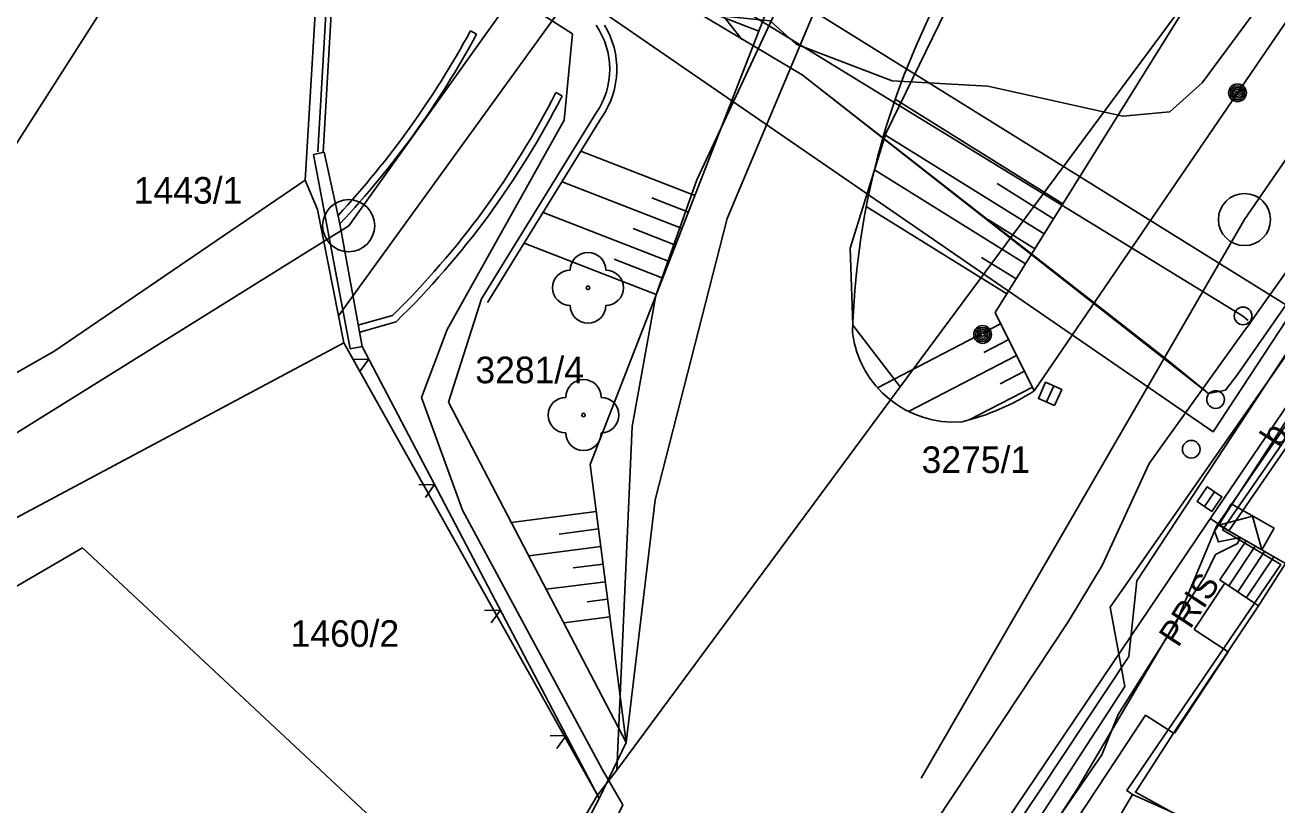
# Model space of a CAD drawing. Extents: x -601580 to 4, y -1204314 to 4.
# Drawn here: x -598974.39 to -598939.03, y -1203990.98 to -1203968.97 of the extents above; entities that cross this region are included whole.
import ezdxf

# ---------------------------------------------------------------- set-up
doc = ezdxf.new("R2010")
doc.units = 0
for name, color, linetype in [('00-EON NN', 7, 'Continuous'), ('00-INNOGY-NTL', 7, 'Continuous'), ('00-KN-HRANICE PARCEL', 7, 'Continuous'), ('00-KN-PARC. CISLA', 7, 'Continuous'), ('00-POLOHOPIS', 7, 'Continuous'), ('00-SITE KOM. KABEL', 7, 'Continuous'), ('00-VAK-KANAL-POTRUBI', 7, 'Continuous'), ('00-VAK-VODA-RAD IGIS', 7, 'Continuous'), ('11-REKONSTRUKCE  VYKOP', 7, 'Continuous'), ('11-REKONSTRUKCE VODOVOD', 7, 'Continuous'), ('11-REKONSTRUKCE VODOVOD POPIS', 7, 'Continuous'), ('Vrstva 22', 7, 'Continuous'), ('Vrstva 25', 7, 'Continuous'), ('Vrstva 27', 7, 'Continuous'), ('Vrstva 28', 7, 'Continuous'), ('Vrstva 9', 7, 'Continuous')]:
    doc.layers.add(name, color=color, linetype=linetype)

# ---------------------------------------------------------------- blocks, each defined once
blk = doc.blocks.new('6.01A_956')
at = {"layer": 'Vrstva 25'}
for radius in [0.25, 0.2, 0.15, 0.1, 0.05]:
    blk.add_circle((0, 0), radius, dxfattribs=at)
blk = doc.blocks.new('3.13_26')
at = {"layer": 'Vrstva 22'}
blk.add_circle((0, 0), 0.05, dxfattribs=at)
for centre, start, end in [((0, 0.5), 0, 180), ((-0.5, 0), 90, 270), ((0.5, 0), 270, 90), ((0, -0.5), 180, 0)]:
    blk.add_arc(centre, 0.5, start, end, dxfattribs=at)
blk = doc.blocks.new('3.13_28')
at = {"layer": 'Vrstva 22'}
blk.add_circle((0, 0), 0.05, dxfattribs=at)
for centre, start, end in [((0, 0.5), 0, 180), ((-0.5, 0), 90, 270), ((0.5, 0), 270, 90), ((0, -0.5), 180, 0)]:
    blk.add_arc(centre, 0.5, start, end, dxfattribs=at)
blk = doc.blocks.new('6.14A_100')
at = {"layer": 'Vrstva 28'}
blk.add_circle((0, 0), 0.25, dxfattribs=at)
blk = doc.blocks.new('6.14A_102')
at = {"layer": 'Vrstva 28'}
blk.add_circle((0, 0), 0.25, dxfattribs=at)
blk = doc.blocks.new('6.14A_104')
at = {"layer": 'Vrstva 28'}
blk.add_circle((0, 0), 0.25, dxfattribs=at)
blk = doc.blocks.new('6.30_46')
at = {"layer": 'Vrstva 27'}
blk.add_line((-0.25, 0), (0.25, 0), dxfattribs=at)
blk.add_lwpolyline([(-0.25, -0.25), (0.25, -0.25), (0.25, 0.25), (-0.25, 0.25)], close=True, dxfattribs=at)
blk = doc.blocks.new('6.30_48')
at = {"layer": 'Vrstva 27'}
blk.add_line((-0.25, 0.001), (0.25, -0.001), dxfattribs=at)
blk.add_lwpolyline([(-0.25, -0.25), (0.25, -0.25), (0.25, 0.25), (-0.25, 0.25)], close=True, dxfattribs=at)
blk = doc.blocks.new('6.01A_1054')
at = {"layer": 'Vrstva 25'}
for radius in [0.25, 0.2, 0.15, 0.1, 0.05]:
    blk.add_circle((0, 0), radius, dxfattribs=at)
blk = doc.blocks.new('NN630')
at = {"layer": 'Vrstva 9'}
for points in [[(-3, -700), (-703, 0)], [(-703, -700), (-703, 0), (697, 0), (697, -700)], [(-3, -700), (697, 0)], [(-703, -700), (697, -700)]]:
    blk.add_lwpolyline(points, dxfattribs=at)

msp = doc.modelspace()

# ---------------------------------------------------------------- linework, layer by layer
at = {"layer": '00-EON NN'}
for points in [[(-598970.68, -1203963.218), (-598969.283, -1203964.296), (-598968.397, -1203965.415), (-598967.498, -1203966.522), (-598965.97, -1203967.918), (-598965.479, -1203967.719), (-598961.435, -1203967.984), (-598957.276, -1203968.45), (-598953.35, -1203968.849), (-598952.613, -1203969.504), (-598949.9, -1203970.541), (-598947.199, -1203970.693), (-598943.383, -1203971.542), (-598942.059, -1203971.414), (-598941.147, -1203970.598), (-598936.353, -1203964.12), (-598934.62, -1203962.058), (-598933.364, -1203961.664), (-598929.2, -1203961.329), (-598925.224, -1203960.211), (-598924.191, -1203959.49), (-598923.41, -1203958.618), (-598917.275, -1203949.663), (-598908.292, -1203936.791)], [(-598965.462, -1203968.121), (-598964.601, -1203968.067), (-598963.511, -1203967.599), (-598962.251, -1203967.089), (-598958.931, -1203969.219), (-598959.161, -1203971.649), (-598962.471, -1203977.559), (-598963.191, -1203979.479), (-598962.031, -1203982.659), (-598958.081, -1203989.989), (-598957.511, -1203990.979), (-598959.671, -1203995.499), (-598962.651, -1203999.729), (-598964.751, -1204003.059), (-598966.021, -1204005.009), (-598966.718, -1204005.819)], [(-598937.681, -1203978.469), (-598940.801, -1203983.259), (-598940.681, -1203983.559), (-598940.071, -1203983.435), (-598940.144, -1203983.599), (-598940.766, -1203983.916), (-598941.078, -1203984.549), (-598941.725, -1203985.545), (-598944.667, -1203990.518), (-598946.985, -1203994.085)]]:
    msp.add_lwpolyline(points, dxfattribs=at)
at = {"layer": '00-INNOGY-NTL'}
msp.add_lwpolyline([(-598947.031, -1203993.329), (-598943.331, -1203987.639), (-598943.741, -1203985.399), (-598938.611, -1203978.059), (-598938.271, -1203977.579), (-598936.341, -1203974.479), (-598935.411, -1203974.309), (-598935.311, -1203974.179), (-598930.491, -1203967.829), (-598928.051, -1203964.079), (-598927.521, -1203963.269), (-598927.641, -1203961.219), (-598924.811, -1203958.379), (-598922.901, -1203955.519), (-598920.671, -1203952.169), (-598915.901, -1203945.359), (-598909.541, -1203936.289), (-598905.021, -1203930.369), (-598901.451, -1203925.719)], dxfattribs=at)
at = {"layer": '00-KN-HRANICE PARCEL'}
for p, q in [((-598950.371, -1203956.229), (-598965.541, -1203977.179)), ((-598966.481, -1203973.349), (-598966.041, -1203965.969)), ((-598966.131, -1203974.179), (-598966.481, -1203973.349)), ((-598965.541, -1203977.179), (-598966.131, -1203974.179)), ((-598965.391, -1203977.939), (-598965.541, -1203977.179)), ((-598985.151, -1203988.489), (-598965.391, -1203977.939)), ((-598958.221, -1203990.709), (-598965.391, -1203977.939)), ((-598949.671, -1203979.179), (-598957.681, -1203989.999)), ((-598957.681, -1203989.999), (-598958.221, -1203990.709)), ((-598960.751, -1203994.939), (-598958.221, -1203990.709))]:
    msp.add_line(p, q, dxfattribs=at)
for points in [[(-598912.531, -1203924.709), (-598912.431, -1203929.039), (-598920.551, -1203939.899), (-598949.671, -1203979.179)], [(-598925.891, -1203925.279), (-598928.511, -1203929.039), (-598935.721, -1203942.609), (-598950.081, -1203972.029), (-598951.091, -1203975.269), (-598951.011, -1203977.439), (-598949.671, -1203979.179)], [(-598957.681, -1203989.999), (-598957.241, -1203980.299), (-598956.571, -1203976.599), (-598955.421, -1203973.339), (-598942.411, -1203945.549), (-598942.941, -1203946.209)], [(-598995.671, -1203992.519), (-598985.941, -1203977.339), (-598982.721, -1203979.379), (-598979.481, -1203974.339), (-598976.971, -1203975.949), (-598970.011, -1203965.069), (-598984.651, -1203955.769), (-598981.531, -1203950.449)], [(-598995.001, -1203992.879), (-598990.001, -1203988.239), (-598985.791, -1203985.299), (-598981.511, -1203982.679), (-598973.581, -1203978.179), (-598966.481, -1203973.349)], [(-598936.661, -1203978.779), (-598937.241, -1203978.409), (-598940.571, -1203983.219), (-598938.921, -1203984.199), (-598943.271, -1203990.579), (-598943.111, -1203990.689)], [(-598960.751, -1203994.939), (-598972.771, -1203983.729), (-598983.821, -1203990.159)], [(-598943.111, -1203990.689), (-598948.191, -1203999.309), (-598947.441, -1203999.799)], [(-598943.111, -1203990.689), (-598941.851, -1203991.249), (-598935.411, -1203994.709), (-598929.461, -1203998.239), (-598921.111, -1204003.439), (-598917.431, -1204005.699)]]:
    msp.add_lwpolyline(points, dxfattribs=at)
at = {"layer": '00-POLOHOPIS'}
for p, q in [((-598922.405, -1203944.89), (-598945.888, -1203979.29)), ((-598941.024, -1203983.056), (-598918.164, -1203949.393)), ((-598946.99, -1203977.084), (-598938.699, -1203963.759)), ((-598958.429, -1203981.374), (-598951.815, -1203964.378)), ((-598954.563, -1203974.426), (-598950.782, -1203965.449)), ((-598965.768, -1203966.486), (-598966.124, -1203972.551)), ((-598965.618, -1203966.495), (-598965.974, -1203972.559)), ((-598957.239, -1203967.752), (-598953.669, -1203969.141)), ((-598961.812, -1203969.132), (-598961.636, -1203969.227)), ((-598959.225, -1203970.966), (-598959.403, -1203970.876)), ((-598949.816, -1203971.065), (-598945.079, -1203974.013)), ((-598961.497, -1203976.695), (-598958.26, -1203971.447)), ((-598961.327, -1203976.8), (-598958.09, -1203971.552)), ((-598950.132, -1203972.046), (-598945.607, -1203974.862)), ((-598966.24, -1203972.626), (-598965.947, -1203972.561)), ((-598965.209, -1203978.106), (-598966.24, -1203972.626)), ((-598965.497, -1203974.579), (-598965.947, -1203972.561)), ((-598958.692, -1203972.528), (-598955.474, -1203973.78)), ((-598950.404, -1203973.055), (-598946.136, -1203975.711)), ((-598959.225, -1203973.393), (-598955.836, -1203974.712)), ((-598946.938, -1203973.445), (-598945.343, -1203974.437)), ((-598956.685, -1203973.845), (-598955.655, -1203974.246)), ((-598950.631, -1203974.091), (-598946.664, -1203976.56)), ((-598959.759, -1203974.258), (-598956.199, -1203975.644)), ((-598956.598, -1203982.373), (-598954.563, -1203974.426)), ((-598947.184, -1203974.47), (-598945.871, -1203975.286)), ((-598964.865, -1203978.043), (-598965.497, -1203974.579)), ((-598957.218, -1203974.71), (-598956.018, -1203975.178)), ((-598960.293, -1203975.124), (-598956.562, -1203976.576)), ((-598957.752, -1203975.576), (-598956.38, -1203976.11)), ((-598947.374, -1203975.529), (-598946.4, -1203976.135)), ((-598962.433, -1203979.613), (-598961.497, -1203976.695)), ((-598964.016, -1203977.167), (-598964.988, -1203977.442)), ((-598963.913, -1203977.346), (-598964.934, -1203977.634)), ((-598945.887, -1203979.289), (-598946.99, -1203977.084)), ((-598950.317, -1203979.204), (-598946.839, -1203977.402)), ((-598965.209, -1203978.106), (-598964.865, -1203978.043)), ((-598947.315, -1203978.212), (-598946.609, -1203977.846)), ((-598949.439, -1203979.875), (-598946.385, -1203978.293)), ((-598946.855, -1203979.1), (-598946.161, -1203978.74)), ((-598947.722, -1203980.112), (-598945.938, -1203979.187)), ((-598957.414, -1203989.217), (-598962.433, -1203979.613)), ((-598957.414, -1203989.217), (-598958.429, -1203981.374)), ((-598957.414, -1203989.217), (-598956.598, -1203982.373)), ((-598960.659, -1203983.008), (-598958.258, -1203982.697)), ((-598940.917, -1203982.897), (-598940.397, -1203983.248)), ((-598959.309, -1203983.337), (-598958.194, -1203983.193)), ((-598955.685, -1204004.762), (-598941.024, -1203983.056)), ((-598960.165, -1203983.952), (-598958.129, -1203983.688)), ((-598939.906, -1203983.528), (-598940.643, -1203984.631)), ((-598939.645, -1203983.677), (-598940.393, -1203984.798)), ((-598939.384, -1203983.826), (-598940.143, -1203984.964)), ((-598939.122, -1203983.975), (-598939.894, -1203985.131)), ((-598958.914, -1203984.294), (-598958.065, -1203984.184)), ((-598959.672, -1203984.896), (-598958.001, -1203984.68)), ((-598940.503, -1203984.725), (-598941.372, -1203986.027)), ((-598940.643, -1203984.631), (-598939.552, -1203985.359)), ((-598958.519, -1203985.251), (-598957.937, -1203985.176)), ((-598959.178, -1203985.841), (-598957.873, -1203985.672)), ((-598941.372, -1203986.027), (-598940.413, -1203986.661)), ((-598941.929, -1203988.955), (-598940.413, -1203986.661)), ((-598948.955, -1203997.835), (-598942.742, -1203988.446)), ((-598942.742, -1203988.446), (-598941.953, -1203988.957))]:
    msp.add_line(p, q, dxfattribs=at)
for points in [[(-598958.18, -1203990.796), (-598964.865, -1203978.043)], [(-598964.941, -1203978.759), (-598964.68, -1203978.396), (-598965.127, -1203978.405)], [(-598938.473, -1203993.186), (-598941.687, -1203991.354), (-598943.033, -1203990.624), (-598941.953, -1203988.957), (-598939.552, -1203985.359), (-598938.792, -1203984.163), (-598940.397, -1203983.248), (-598937.06, -1203978.41), (-598932.944, -1203981.249)], [(-598963.084, -1203982.302), (-598962.823, -1203981.939), (-598963.27, -1203981.948)], [(-598961.227, -1203985.845), (-598960.966, -1203985.482), (-598961.413, -1203985.49)], [(-598959.37, -1203989.388), (-598959.109, -1203989.025), (-598959.556, -1203989.033)], [(-598958.18, -1203990.796), (-598957.414, -1203989.217)], [(-598960.436, -1203995.108), (-598958.18, -1203990.796)]]:
    msp.add_lwpolyline(points, dxfattribs=at)
for centre, radius, start, end in [((-598929.154, -1203978.249), 21.875, 153.5006, 178.4328), ((-598984.305, -1203956.942), 25.584, 317.1461, 331.5454), ((-598960.062, -1203970.212), 2.185, 325.56, 34.6711), ((-598960.062, -1203970.212), 2.385, 325.56, 31.4145), ((-598984.305, -1203956.942), 25.784, 316.8403, 331.5453), ((-598980.786, -1203960.034), 23.975, 314.3854, 333.1117), ((-598980.786, -1203960.034), 24.175, 314.2646, 333.1117), ((-598948.159, -1203977.29), 2.885, 187.1746, 274.6126), ((-598949.488, -1203973.718), 6.634, 283.6063, 302.8722)]:
    msp.add_arc(centre, radius, start, end, dxfattribs=at)
at = {"layer": '00-SITE KOM. KABEL'}
for points in [[(-598983.211, -1204049.029), (-598984.421, -1204048.099), (-598967.311, -1204022.559), (-598957.421, -1204007.979), (-598945.701, -1203990.539), (-598943.221, -1203986.789), (-598942.991, -1203984.659), (-598936.941, -1203975.459), (-598934.621, -1203973.279), (-598927.721, -1203962.939), (-598909.841, -1203938.099), (-598898.481, -1203923.139)], [(-598946.581, -1203993.339), (-598943.981, -1203989.569), (-598943.521, -1203988.429), (-598941.871, -1203985.819), (-598940.741, -1203983.109), (-598938.401, -1203979.709)]]:
    msp.add_lwpolyline(points, dxfattribs=at)
at = {"layer": '00-VAK-KANAL-POTRUBI'}
msp.add_line((-598939.951, -1203974.459), (-598949.085, -1203990.231), dxfattribs=at)
for points in [[(-598926.897, -1203921.011), (-598952.204, -1203956.392), (-598965.25, -1203974.632)], [(-598913.85, -1203936.567), (-598939.951, -1203974.459)], [(-598989.267, -1203989.597), (-598965.25, -1203974.632)]]:
    msp.add_lwpolyline(points, dxfattribs=at)
for centre in [(-598939.951, -1203974.459), (-598965.25, -1203974.632)]:
    msp.add_circle(centre, 0.735, dxfattribs=at)
at = {"layer": '00-VAK-VODA-RAD IGIS'}
for points in [[(-598890.171, -1203908.998), (-598904.341, -1203927.128), (-598911.961, -1203937.278), (-598926.551, -1203958.708), (-598939.703, -1203977.252)], [(-598890.211, -1203909.878), (-598904.081, -1203927.358), (-598911.611, -1203937.618), (-598926.131, -1203958.708), (-598940.151, -1203978.828)], [(-598940.006, -1203977.181), (-598959.324, -1203965.344), (-598957.772, -1203963.198)], [(-598940.968, -1203979.371), (-598942.093, -1203978.443), (-598952.44, -1203970.378), (-598961.592, -1203964.913), (-598960.869, -1203963.772)], [(-598939.842, -1203977.308), (-598940.006, -1203977.181)], [(-598939.703, -1203977.252), (-598939.821, -1203977.418)], [(-598939.946, -1203977.592), (-598942.641, -1203981.348), (-598943.971, -1203984.228), (-598944.931, -1203985.818), (-598956.591, -1204003.418), (-598965.731, -1204017.208), (-598974.871, -1204031.008), (-598977.061, -1204033.198), (-598983.911, -1204044.168), (-598986.961, -1204049.468), (-598990.591, -1204056.048), (-598994.634, -1204063.36), (-599001.351, -1204075.798), (-599010.001, -1204098.838), (-599016.452, -1204114.902), (-599018.717, -1204120.54), (-599024.191, -1204130.198), (-599033.501, -1204145.528), (-599038.841, -1204153.758), (-599042.18, -1204157.387), (-599042.541, -1204158.028)], [(-598939.821, -1203977.418), (-598939.946, -1203977.592)], [(-598940.151, -1203978.828), (-598940.491, -1203979.278), (-598940.968, -1203979.372)]]:
    msp.add_lwpolyline(points, dxfattribs=at)
at = {"layer": '11-REKONSTRUKCE  VYKOP'}
msp.add_lwpolyline([(-598959.478, -1203960.069), (-598956.159, -1203962.475), (-598957.874, -1203964.992), (-598938.57, -1203976.994), (-598940.838, -1203980.451), (-598963.35, -1203964.964), (-598959.478, -1203960.069)], dxfattribs=at)
at = {"layer": '11-REKONSTRUKCE VODOVOD'}
msp.add_lwpolyline([(-598960.869, -1203963.772), (-598961.231, -1203964.343), (-598961.592, -1203964.913), (-598952.44, -1203970.378), (-598940.968, -1203979.371)], dxfattribs=at)
at = {"layer": '11-REKONSTRUKCE VODOVOD POPIS'}
msp.add_line((-598973.083, -1203945.201), (-598954.136, -1203969.389), dxfattribs=at)

# ---------------------------------------------------------------- block references
at = {"layer": '00-EON NN', "xscale": 0.0009999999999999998, "yscale": 0.0009999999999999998, "rotation": 150.3128194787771}
msp.add_blockref('NN630', (-598940.071, -1203983.434), dxfattribs=at)
at = {"layer": '00-POLOHOPIS'}
for name, p, xscale, yscale, rotation in [('6.01A_1054', (-598940.148, -1203970.881), 1.00000188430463, 1.00000188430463, 150.0012946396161), ('6.30_48', (-598945.441, -1203979.379), 0.99999834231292, 0.99999834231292, 66.04284774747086), ('6.30_46', (-598940.935, -1203982.353), 0.9999999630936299, 0.9999999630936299, 55.62765186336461)]:
    msp.add_blockref(name, p, dxfattribs=dict(at, xscale=xscale, yscale=yscale, rotation=rotation))
for name, p, rotation in [('3.13_28', (-598958.491, -1203976.384), 180), ('6.14A_104', (-598939.991, -1203977.179), -90.00000000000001), ('6.01A_956', (-598947.345, -1203977.703), -90.00000000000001), ('3.13_26', (-598958.618, -1203979.977), 180), ('6.14A_102', (-598940.765, -1203979.539), -90.00000000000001), ('6.14A_100', (-598941.453, -1203980.944), -90.00000000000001)]:
    msp.add_blockref(name, p, dxfattribs=dict(at, rotation=rotation))

# ---------------------------------------------------------------- texts
at = {"layer": '00-KN-PARC. CISLA'}
for s, p in [('1443/1', (-598971.32, -1203974.009)), ('3281/4', (-598961.672, -1203979.079)), ('3275/1', (-598949.07, -1203981.613)), ('1460/2', (-598966.892, -1203986.519))]:
    msp.add_text(s, height=0.75, dxfattribs=at).set_placement(p)
at = {"layer": '00-POLOHOPIS'}
for s, rotation, p in [('b.', 57.9182, (-598938.955, -1203980.929)), ('PRIS', 56.5935, (-598941.826, -1203986.565))]:
    msp.add_text(s, height=0.7, rotation=rotation, dxfattribs=at).set_placement(p)

doc.saveas('drawing.dxf')
